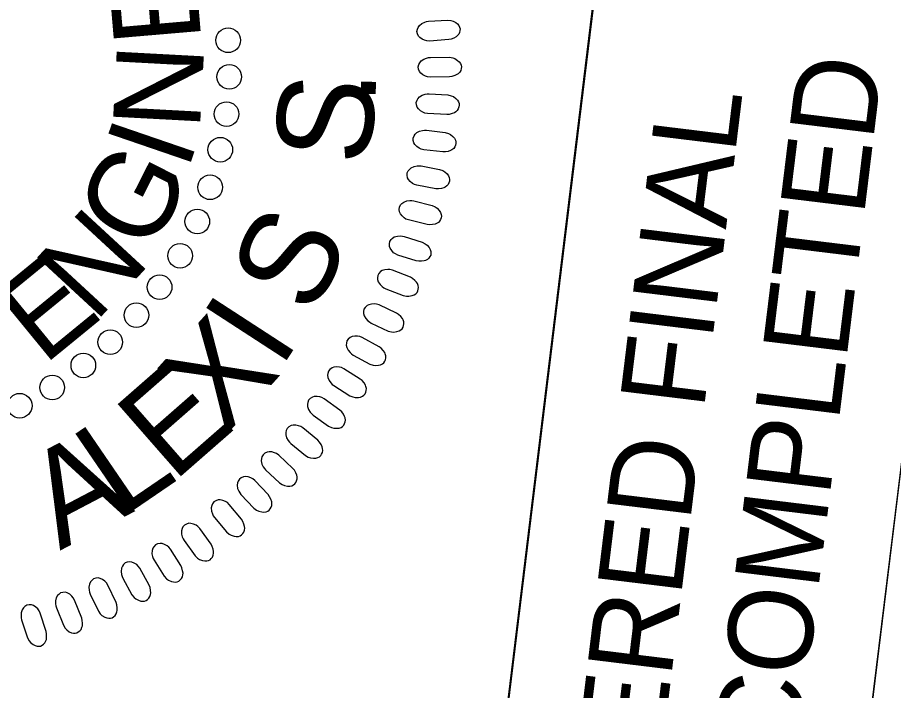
# Model space of a CAD drawing. Extents: x 480344 to 482186, y 488805 to 491553.
# Drawn here: x 480946.7 to 481003.7, y 490486.4 to 490530.1 of the extents above; entities that cross this region are included whole.
import ezdxf

# ---------------------------------------------------------------- set-up
doc = ezdxf.new("R2010")
doc.units = 0
for name, color, linetype in [('Sheet Layout Plan Border', 7, 'Continuous'), ('Sheet PE Seal Cell', 7, 'Continuous'), ('Sheet Plan CELL', 7, 'Continuous'), ('Sheet Sticker Exception Certification CELL', 7, 'Continuous')]:
    doc.layers.add(name, color=color, linetype=linetype)

msp = doc.modelspace()

# ---------------------------------------------------------------- linework, layer by layer
at = {"layer": 'Sheet Layout Plan Border'}
msp.add_lwpolyline([(481703.226, 488995.253), (481861.691, 490292.688), (481782.266, 490302.389), (481802.944, 490471.693), (481574.795, 490460.718), (481089.788, 490519.955), (481007.711, 490529.98), (480988.134, 490369.7), (480815.851, 490390.73), (480660.971, 489122.552)], close=True, dxfattribs=at)
at = {"layer": 'Sheet PE Seal Cell'}
for points in [[(480973.467, 490529.894), (480974.691, 490529.975), (480974.912, 490529.953), (480975.055, 490529.91), (480975.232, 490529.81), (480975.348, 490529.719), (480975.435, 490529.613), (480975.482, 490529.511), (480975.509, 490529.4), (480975.496, 490529.288), (480975.474, 490529.166), (480975.422, 490529.058), (480975.329, 490528.947), (480975.254, 490528.882), (480975.109, 490528.805), (480974.934, 490528.733), (480974.776, 490528.7), (480973.523, 490528.609), (480973.352, 490528.62), (480973.209, 490528.656), (480973.045, 490528.734), (480972.898, 490528.836), (480972.811, 490528.929), (480972.742, 490529.081), (480972.712, 490529.229), (480972.742, 490529.381), (480972.784, 490529.489), (480972.875, 490529.622), (480973.036, 490529.753), (480973.212, 490529.832), (480973.338, 490529.87)], [(480973.594, 490527.546), (480974.82, 490527.551), (480975.04, 490527.514), (480975.18, 490527.463), (480975.35, 490527.351), (480975.46, 490527.254), (480975.54, 490527.142), (480975.58, 490527.038), (480975.601, 490526.926), (480975.581, 490526.814), (480975.552, 490526.694), (480975.493, 490526.589), (480975.393, 490526.484), (480975.313, 490526.424), (480975.164, 490526.356), (480974.985, 490526.295), (480974.825, 490526.273), (480973.569, 490526.26), (480973.399, 490526.282), (480973.259, 490526.327), (480973.1, 490526.416), (480972.96, 490526.527), (480972.879, 490526.624), (480972.819, 490526.781), (480972.798, 490526.931), (480972.838, 490527.08), (480972.888, 490527.185), (480972.986, 490527.312), (480973.155, 490527.432), (480973.335, 490527.5), (480973.464, 490527.53)], [(480973.499, 490525.174), (480974.724, 490525.102), (480974.941, 490525.052), (480975.077, 490524.992), (480975.24, 490524.869), (480975.344, 490524.766), (480975.416, 490524.649), (480975.45, 490524.543), (480975.463, 490524.429), (480975.436, 490524.319), (480975.4, 490524.201), (480975.334, 490524.1), (480975.228, 490524.001), (480975.145, 490523.947), (480974.992, 490523.888), (480974.809, 490523.839), (480974.648, 490523.826), (480973.393, 490523.893), (480973.225, 490523.925), (480973.089, 490523.979), (480972.935, 490524.078), (480972.802, 490524.197), (480972.728, 490524.299), (480972.678, 490524.459), (480972.667, 490524.61), (480972.715, 490524.757), (480972.771, 490524.858), (480972.878, 490524.979), (480973.055, 490525.089), (480973.238, 490525.145), (480973.369, 490525.168)], [(480973.334, 490522.81), (480974.552, 490522.661), (480974.764, 490522.597), (480974.897, 490522.528), (480975.052, 490522.396), (480975.149, 490522.286), (480975.214, 490522.165), (480975.241, 490522.057), (480975.247, 490521.943), (480975.214, 490521.834), (480975.17, 490521.719), (480975.098, 490521.622), (480974.986, 490521.531), (480974.899, 490521.481), (480974.742, 490521.432), (480974.557, 490521.395), (480974.396, 490521.392), (480973.148, 490521.537), (480972.983, 490521.58), (480972.849, 490521.642), (480972.702, 490521.75), (480972.577, 490521.878), (480972.509, 490521.985), (480972.469, 490522.148), (480972.468, 490522.299), (480972.525, 490522.442), (480972.588, 490522.54), (480972.701, 490522.655), (480972.884, 490522.752), (480973.071, 490522.797), (480973.203, 490522.81)], [(480972.977, 490520.483), (480974.183, 490520.257), (480974.392, 490520.18), (480974.52, 490520.104), (480974.666, 490519.962), (480974.756, 490519.846), (480974.813, 490519.722), (480974.834, 490519.611), (480974.832, 490519.497), (480974.792, 490519.391), (480974.741, 490519.279), (480974.663, 490519.187), (480974.546, 490519.103), (480974.456, 490519.058), (480974.297, 490519.02), (480974.109, 490518.994), (480973.948, 490519.001), (480972.712, 490519.224), (480972.549, 490519.278), (480972.42, 490519.348), (480972.28, 490519.465), (480972.163, 490519.6), (480972.103, 490519.711), (480972.073, 490519.876), (480972.081, 490520.027), (480972.148, 490520.167), (480972.216, 490520.26), (480972.337, 490520.367), (480972.526, 490520.453), (480972.715, 490520.487), (480972.847, 490520.492)], [(480972.5, 490518.207), (480973.69, 490517.906), (480973.893, 490517.816), (480974.016, 490517.731), (480974.153, 490517.581), (480974.235, 490517.46), (480974.286, 490517.331), (480974.298, 490517.22), (480974.29, 490517.106), (480974.243, 490517.003), (480974.185, 490516.894), (480974.102, 490516.807), (480973.979, 490516.731), (480973.887, 490516.692), (480973.725, 490516.664), (480973.537, 490516.649), (480973.377, 490516.667), (480972.157, 490516.967), (480971.998, 490517.031), (480971.873, 490517.109), (480971.741, 490517.234), (480971.632, 490517.377), (480971.579, 490517.491), (480971.559, 490517.658), (480971.577, 490517.808), (480971.652, 490517.943), (480971.726, 490518.032), (480971.854, 490518.131), (480972.047, 490518.205), (480972.238, 490518.227), (480972.371, 490518.224)], [(480971.89, 490515.897), (480973.058, 490515.523), (480973.255, 490515.42), (480973.373, 490515.328), (480973.5, 490515.169), (480973.574, 490515.043), (480973.616, 490514.912), (480973.622, 490514.8), (480973.606, 490514.687), (480973.554, 490514.587), (480973.489, 490514.482), (480973.4, 490514.401), (480973.273, 490514.332), (480973.179, 490514.299), (480973.016, 490514.28), (480972.826, 490514.278), (480972.667, 490514.306), (480971.469, 490514.682), (480971.314, 490514.756), (480971.195, 490514.841), (480971.07, 490514.975), (480970.972, 490515.124), (480970.925, 490515.241), (480970.916, 490515.409), (480970.943, 490515.558), (480971.027, 490515.687), (480971.106, 490515.772), (480971.239, 490515.863), (480971.437, 490515.924), (480971.629, 490515.934), (480971.761, 490515.923)], [(480970.681, 490512.497), (480971.823, 490512.05), (480972.04, 490512.005), (480972.19, 490512.002), (480972.389, 490512.045), (480972.527, 490512.095), (480972.641, 490512.171), (480972.717, 490512.253), (480972.776, 490512.351), (480972.798, 490512.462), (480972.814, 490512.585), (480972.797, 490512.704), (480972.742, 490512.837), (480972.69, 490512.922), (480972.575, 490513.039), (480972.429, 490513.161), (480972.289, 490513.24), (480971.122, 490513.705), (480970.956, 490513.746), (480970.809, 490513.755), (480970.628, 490513.729), (480970.457, 490513.676), (480970.347, 490513.614), (480970.234, 490513.49), (480970.162, 490513.358), (480970.144, 490513.204), (480970.153, 490513.089), (480970.199, 490512.934), (480970.313, 490512.761), (480970.456, 490512.633), (480970.566, 490512.558)], [(480969.73, 490510.263), (480970.842, 490509.745), (480971.057, 490509.686), (480971.205, 490509.674), (480971.406, 490509.704), (480971.547, 490509.746), (480971.667, 490509.815), (480971.746, 490509.892), (480971.812, 490509.985), (480971.841, 490510.095), (480971.865, 490510.217), (480971.855, 490510.337), (480971.808, 490510.474), (480971.761, 490510.561), (480971.654, 490510.686), (480971.517, 490510.815), (480971.382, 490510.904), (480970.246, 490511.441), (480970.082, 490511.492), (480969.937, 490511.51), (480969.755, 490511.496), (480969.581, 490511.454), (480969.467, 490511.399), (480969.347, 490511.283), (480969.266, 490511.155), (480969.239, 490511.003), (480969.24, 490510.887), (480969.276, 490510.73), (480969.379, 490510.55), (480969.514, 490510.413), (480969.619, 490510.331)], [(480968.567, 490508.18), (480969.644, 490507.593), (480969.855, 490507.521), (480970.002, 490507.499), (480970.205, 490507.517), (480970.348, 490507.55), (480970.471, 490507.611), (480970.556, 490507.683), (480970.628, 490507.772), (480970.663, 490507.88), (480970.695, 490508), (480970.693, 490508.12), (480970.654, 490508.259), (480970.613, 490508.35), (480970.514, 490508.481), (480970.385, 490508.619), (480970.256, 490508.716), (480969.156, 490509.323), (480968.996, 490509.385), (480968.852, 490509.411), (480968.669, 490509.409), (480968.493, 490509.378), (480968.376, 490509.33), (480968.248, 490509.221), (480968.159, 490509.099), (480968.123, 490508.949), (480968.117, 490508.833), (480968.143, 490508.674), (480968.235, 490508.488), (480968.361, 490508.343), (480968.46, 490508.255)], [(480967.308, 490506.19), (480968.346, 490505.537), (480968.552, 490505.452), (480968.698, 490505.421), (480968.901, 490505.426), (480969.046, 490505.45), (480969.173, 490505.502), (480969.262, 490505.569), (480969.339, 490505.654), (480969.381, 490505.76), (480969.42, 490505.877), (480969.425, 490505.997), (480969.396, 490506.139), (480969.361, 490506.232), (480969.27, 490506.369), (480969.15, 490506.515), (480969.027, 490506.619), (480967.968, 490507.294), (480967.812, 490507.366), (480967.67, 490507.402), (480967.487, 490507.412), (480967.309, 490507.391), (480967.19, 490507.351), (480967.056, 490507.25), (480966.959, 490507.134), (480966.913, 490506.986), (480966.9, 490506.871), (480966.916, 490506.71), (480966.996, 490506.519), (480967.113, 490506.366), (480967.206, 490506.272)], [(480965.96, 490504.28), (480966.955, 490503.563), (480967.155, 490503.465), (480967.299, 490503.425), (480967.502, 490503.417), (480967.648, 490503.432), (480967.778, 490503.476), (480967.872, 490503.538), (480967.954, 490503.618), (480968.002, 490503.72), (480968.048, 490503.834), (480968.062, 490503.954), (480968.041, 490504.097), (480968.012, 490504.192), (480967.93, 490504.335), (480967.819, 490504.488), (480967.703, 490504.6), (480966.687, 490505.34), (480966.537, 490505.421), (480966.397, 490505.466), (480966.215, 490505.487), (480966.037, 490505.478), (480965.915, 490505.446), (480965.775, 490505.353), (480965.671, 490505.243), (480965.616, 490505.099), (480965.595, 490504.985), (480965.602, 490504.824), (480965.67, 490504.628), (480965.776, 490504.468), (480965.863, 490504.368)], [(480964.509, 490502.425), (480965.458, 490501.646), (480965.65, 490501.536), (480965.791, 490501.487), (480965.994, 490501.466), (480966.14, 490501.472), (480966.273, 490501.508), (480966.37, 490501.563), (480966.456, 490501.638), (480966.512, 490501.737), (480966.566, 490501.848), (480966.585, 490501.967), (480966.575, 490502.111), (480966.551, 490502.209), (480966.478, 490502.355), (480966.377, 490502.515), (480966.268, 490502.634), (480965.302, 490503.437), (480965.156, 490503.527), (480965.02, 490503.581), (480964.84, 490503.613), (480964.661, 490503.615), (480964.537, 490503.59), (480964.391, 490503.508), (480964.281, 490503.404), (480964.217, 490503.263), (480964.189, 490503.15), (480964.185, 490502.989), (480964.241, 490502.79), (480964.337, 490502.623), (480964.418, 490502.518)], [(480962.875, 490500.708), (480963.773, 490499.872), (480963.959, 490499.75), (480964.097, 490499.692), (480964.298, 490499.659), (480964.444, 490499.655), (480964.579, 490499.683), (480964.679, 490499.732), (480964.771, 490499.801), (480964.832, 490499.896), (480964.892, 490500.005), (480964.92, 490500.122), (480964.918, 490500.266), (480964.901, 490500.364), (480964.836, 490500.515), (480964.746, 490500.681), (480964.645, 490500.807), (480963.731, 490501.669), (480963.591, 490501.768), (480963.458, 490501.83), (480963.281, 490501.874), (480963.102, 490501.888), (480962.978, 490501.87), (480962.826, 490501.797), (480962.71, 490501.7), (480962.637, 490501.563), (480962.603, 490501.453), (480962.588, 490501.292), (480962.632, 490501.09), (480962.717, 490500.917), (480962.791, 490500.807)], [(480961.269, 490499.11), (480962.113, 490498.219), (480962.291, 490498.085), (480962.424, 490498.019), (480962.622, 490497.974), (480962.769, 490497.961), (480962.905, 490497.98), (480963.009, 490498.022), (480963.104, 490498.085), (480963.171, 490498.176), (480963.237, 490498.281), (480963.272, 490498.396), (480963.279, 490498.541), (480963.269, 490498.64), (480963.215, 490498.795), (480963.135, 490498.966), (480963.041, 490499.098), (480962.183, 490500.015), (480962.05, 490500.123), (480961.921, 490500.193), (480961.747, 490500.248), (480961.57, 490500.272), (480961.443, 490500.263), (480961.289, 490500.199), (480961.166, 490500.11), (480961.085, 490499.979), (480961.044, 490499.87), (480961.02, 490499.711), (480961.05, 490499.506), (480961.124, 490499.328), (480961.191, 490499.214)], [(480959.546, 490497.618), (480960.331, 490496.676), (480960.5, 490496.531), (480960.63, 490496.458), (480960.825, 490496.399), (480960.97, 490496.377), (480961.107, 490496.387), (480961.212, 490496.424), (480961.312, 490496.48), (480961.384, 490496.567), (480961.457, 490496.667), (480961.5, 490496.78), (480961.516, 490496.924), (480961.511, 490497.023), (480961.467, 490497.182), (480961.398, 490497.357), (480961.313, 490497.495), (480960.514, 490498.464), (480960.388, 490498.58), (480960.264, 490498.658), (480960.093, 490498.724), (480959.918, 490498.759), (480959.792, 490498.758), (480959.633, 490498.704), (480959.505, 490498.623), (480959.416, 490498.497), (480959.368, 490498.391), (480959.334, 490498.234), (480959.351, 490498.027), (480959.414, 490497.845), (480959.474, 490497.727)], [(480957.57, 490496.111), (480958.295, 490495.121), (480958.454, 490494.967), (480958.579, 490494.885), (480958.77, 490494.814), (480958.913, 490494.783), (480959.051, 490494.785), (480959.159, 490494.814), (480959.261, 490494.865), (480959.34, 490494.947), (480959.419, 490495.042), (480959.467, 490495.152), (480959.493, 490495.295), (480959.494, 490495.394), (480959.46, 490495.555), (480959.402, 490495.735), (480959.326, 490495.877), (480958.59, 490496.895), (480958.471, 490497.019), (480958.352, 490497.104), (480958.186, 490497.18), (480958.013, 490497.227), (480957.888, 490497.233), (480957.725, 490497.189), (480957.593, 490497.117), (480957.496, 490496.996), (480957.441, 490496.894), (480957.397, 490496.739), (480957.401, 490496.531), (480957.453, 490496.346), (480957.506, 490496.225)], [(480955.63, 490494.827), (480956.291, 490493.793), (480956.44, 490493.629), (480956.56, 490493.539), (480956.746, 490493.457), (480956.886, 490493.417), (480957.024, 490493.41), (480957.133, 490493.433), (480957.239, 490493.477), (480957.322, 490493.554), (480957.407, 490493.644), (480957.463, 490493.75), (480957.497, 490493.891), (480957.505, 490493.99), (480957.481, 490494.153), (480957.434, 490494.336), (480957.368, 490494.482), (480956.696, 490495.545), (480956.586, 490495.676), (480956.472, 490495.769), (480956.311, 490495.855), (480956.142, 490495.913), (480956.017, 490495.927), (480955.852, 490495.893), (480955.716, 490495.829), (480955.612, 490495.715), (480955.55, 490495.616), (480955.496, 490495.464), (480955.487, 490495.257), (480955.527, 490495.069), (480955.572, 490494.944)], [(480953.592, 490493.662), (480954.187, 490492.589), (480954.326, 490492.415), (480954.439, 490492.318), (480954.62, 490492.224), (480954.758, 490492.176), (480954.895, 490492.161), (480955.005, 490492.176), (480955.114, 490492.213), (480955.202, 490492.285), (480955.292, 490492.369), (480955.355, 490492.472), (480955.397, 490492.61), (480955.411, 490492.709), (480955.397, 490492.873), (480955.363, 490493.058), (480955.305, 490493.209), (480954.702, 490494.311), (480954.6, 490494.449), (480954.493, 490494.549), (480954.337, 490494.645), (480954.172, 490494.713), (480954.048, 490494.736), (480953.881, 490494.712), (480953.741, 490494.656), (480953.63, 490494.549), (480953.562, 490494.455), (480953.499, 490494.306), (480953.477, 490494.1), (480953.505, 490493.91), (480953.542, 490493.782)], [(480951.477, 490492.634), (480952.004, 490491.526), (480952.131, 490491.344), (480952.238, 490491.24), (480952.413, 490491.135), (480952.547, 490491.078), (480952.683, 490491.054), (480952.794, 490491.063), (480952.904, 490491.093), (480952.997, 490491.159), (480953.092, 490491.238), (480953.161, 490491.336), (480953.213, 490491.471), (480953.232, 490491.569), (480953.229, 490491.733), (480953.206, 490491.921), (480953.158, 490492.074), (480952.625, 490493.213), (480952.532, 490493.356), (480952.431, 490493.463), (480952.282, 490493.569), (480952.121, 490493.647), (480951.999, 490493.677), (480951.831, 490493.664), (480951.688, 490493.618), (480951.57, 490493.518), (480951.497, 490493.428), (480951.425, 490493.283), (480951.39, 490493.078), (480951.406, 490492.887), (480951.435, 490492.757)], [(480949.277, 490491.738), (480949.733, 490490.599), (480949.849, 490490.409), (480949.95, 490490.299), (480950.116, 490490.183), (480950.248, 490490.117), (480950.381, 490490.085), (480950.493, 490490.087), (480950.605, 490490.11), (480950.701, 490490.171), (480950.801, 490490.243), (480950.876, 490490.337), (480950.936, 490490.469), (480950.963, 490490.565), (480950.969, 490490.729), (480950.958, 490490.918), (480950.92, 490491.074), (480950.46, 490492.244), (480950.375, 490492.393), (480950.282, 490492.505), (480950.139, 490492.62), (480949.984, 490492.708), (480949.864, 490492.746), (480949.696, 490492.743), (480949.549, 490492.706), (480949.425, 490492.613), (480949.347, 490492.528), (480949.266, 490492.389), (480949.218, 490492.187), (480949.222, 490491.995), (480949.243, 490491.864)], [(480947.017, 490490.959), (480947.401, 490489.793), (480947.505, 490489.597), (480947.598, 490489.48), (480947.758, 490489.355), (480947.885, 490489.28), (480948.016, 490489.24), (480948.128, 490489.235), (480948.241, 490489.251), (480948.34, 490489.305), (480948.445, 490489.371), (480948.526, 490489.46), (480948.594, 490489.588), (480948.626, 490489.682), (480948.643, 490489.845), (480948.643, 490490.035), (480948.615, 490490.193), (480948.23, 490491.389), (480948.155, 490491.543), (480948.069, 490491.662), (480947.934, 490491.785), (480947.784, 490491.883), (480947.666, 490491.928), (480947.498, 490491.936), (480947.35, 490491.908), (480947.221, 490491.823), (480947.137, 490491.743), (480947.047, 490491.609), (480946.987, 490491.411), (480946.979, 490491.219), (480946.991, 490491.087)]]:
    msp.add_lwpolyline(points, close=True, dxfattribs=at)
for centre in [(480960.439, 490528.656), (480960.509, 490526.281), (480960.333, 490523.856), (480959.928, 490521.539), (480959.268, 490519.093), (480958.433, 490516.868), (480957.317, 490514.639), (480955.984, 490512.596), (480954.476, 490510.775), (480952.776, 490509.018), (480951.026, 490507.507), (480949.004, 490506.07), (480946.892, 490504.885)]:
    msp.add_circle(centre, 0.801, dxfattribs=at)
at = {"layer": 'Sheet Plan CELL'}
msp.add_line((480964.808, 490372.549), (480989.072, 490571.11), dxfattribs=at)
msp.add_lwpolyline([(480865.278, 490485.486), (480877.388, 490584.738), (480989.072, 490571.11), (480976.961, 490471.846)], close=True, dxfattribs=at)
at = {"layer": 'Sheet Sticker Exception Certification CELL'}
for p, q in [((480964.808, 490372.549), (480989.06, 490571.111)), ((480964.808, 490372.549), (480989.06, 490571.111)), ((480964.808, 490372.549), (480989.06, 490571.111)), ((481012.386, 490568.262), (480988.134, 490369.7)), ((481012.386, 490568.262), (480988.134, 490369.7)), ((481012.386, 490568.262), (480988.134, 490369.7))]:
    msp.add_line(p, q, dxfattribs=at)

# ---------------------------------------------------------------- texts
at = {"layer": 'Sheet PE Seal Cell'}
for s, height, rotation, p in [('E', 5.669, 94.8807, (480958.703, 490528.641)), ('N', 5.669, 86.9409, (480958.596, 490522.763)), ('S', 6.236, 82.4191, (480969.486, 490520.392)), ('.', 6.236, 89.2648, (480970.024, 490524.396)), ('I', 5.669, 71.0613, (480957.793, 490520.087)), ('G', 5.669, 63.1215, (480955.434, 490514.705)), ('N', 5.669, 47.2419, (480951.765, 490510.222)), ('S', 6.236, 63.8239, (480965.953, 490510.627)), ('E', 5.669, 39.3021, (480948.451, 490507.469)), ('I', 6.236, 56.9783, (480963.829, 490507.204)), ('X', 6.236, 48.0309, (480960.215, 490502.861)), ('E', 6.236, 41.1853, (480956.852, 490499.845)), ('L', 6.236, 34.3396, (480953.464, 490497.526)), ('A', 6.236, 27.72, (480949.503, 490495.45))]:
    msp.add_text(s, height=height, rotation=rotation, dxfattribs=at).set_placement(p)
at = {"layer": 'Sheet Sticker Exception Certification CELL'}
for s, p in [('UNLESS ALL SIGNATURES COMPLETED', (480985.752, 490386.11)), ('UNLESS ALL SIGNATURES COMPLETED', (480985.752, 490386.11)), ('UNLESS ALL SIGNATURES COMPLETED', (480985.752, 490386.11)), ('DOCUMENT NOT CONSIDERED FINAL', (480977.631, 490392.21)), ('DOCUMENT NOT CONSIDERED FINAL', (480977.631, 490392.21)), ('DOCUMENT NOT CONSIDERED FINAL', (480977.631, 490392.21))]:
    msp.add_text(s, height=5.5, rotation=83.0365, dxfattribs=at).set_placement(p)

doc.saveas('drawing.dxf')
